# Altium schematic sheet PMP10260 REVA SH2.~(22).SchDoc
size 431 x 279 mm; Date: Not shown in title block; ApprovedBy: Not shown in title block; CheckedBy: Not shown in title block; Author: Not shown in title block; CompanyName: Not shown in title block; Engineer: Not shown in title block; Organization: Not shown in title block; Address1: Not shown in title block; Address2: Not shown in title block; Address3: Not shown in title block; Address4: Not shown in title block; DocumentNumber: 2; Revision: Use project parameter SCH_Rev; SheetNumber: 2; SheetTotal: 3; PageSetup: Record=PageOptions|CenterHorizontal=True|CenterVertical=True|PrintScale=1.00|XCorrection=1.00|YCorrection=1.00|PrintKind=0|BorderSize=5000000|LeftOffset=0|BottomOffset=0|Orientation=2|PaperLength=1000|PaperWidth=1000|Scale=100|PaperSource=15|PrintQuality=600|MediaType=1|DitherType=10|PaperKind=Letter|PrintScaleMode=1
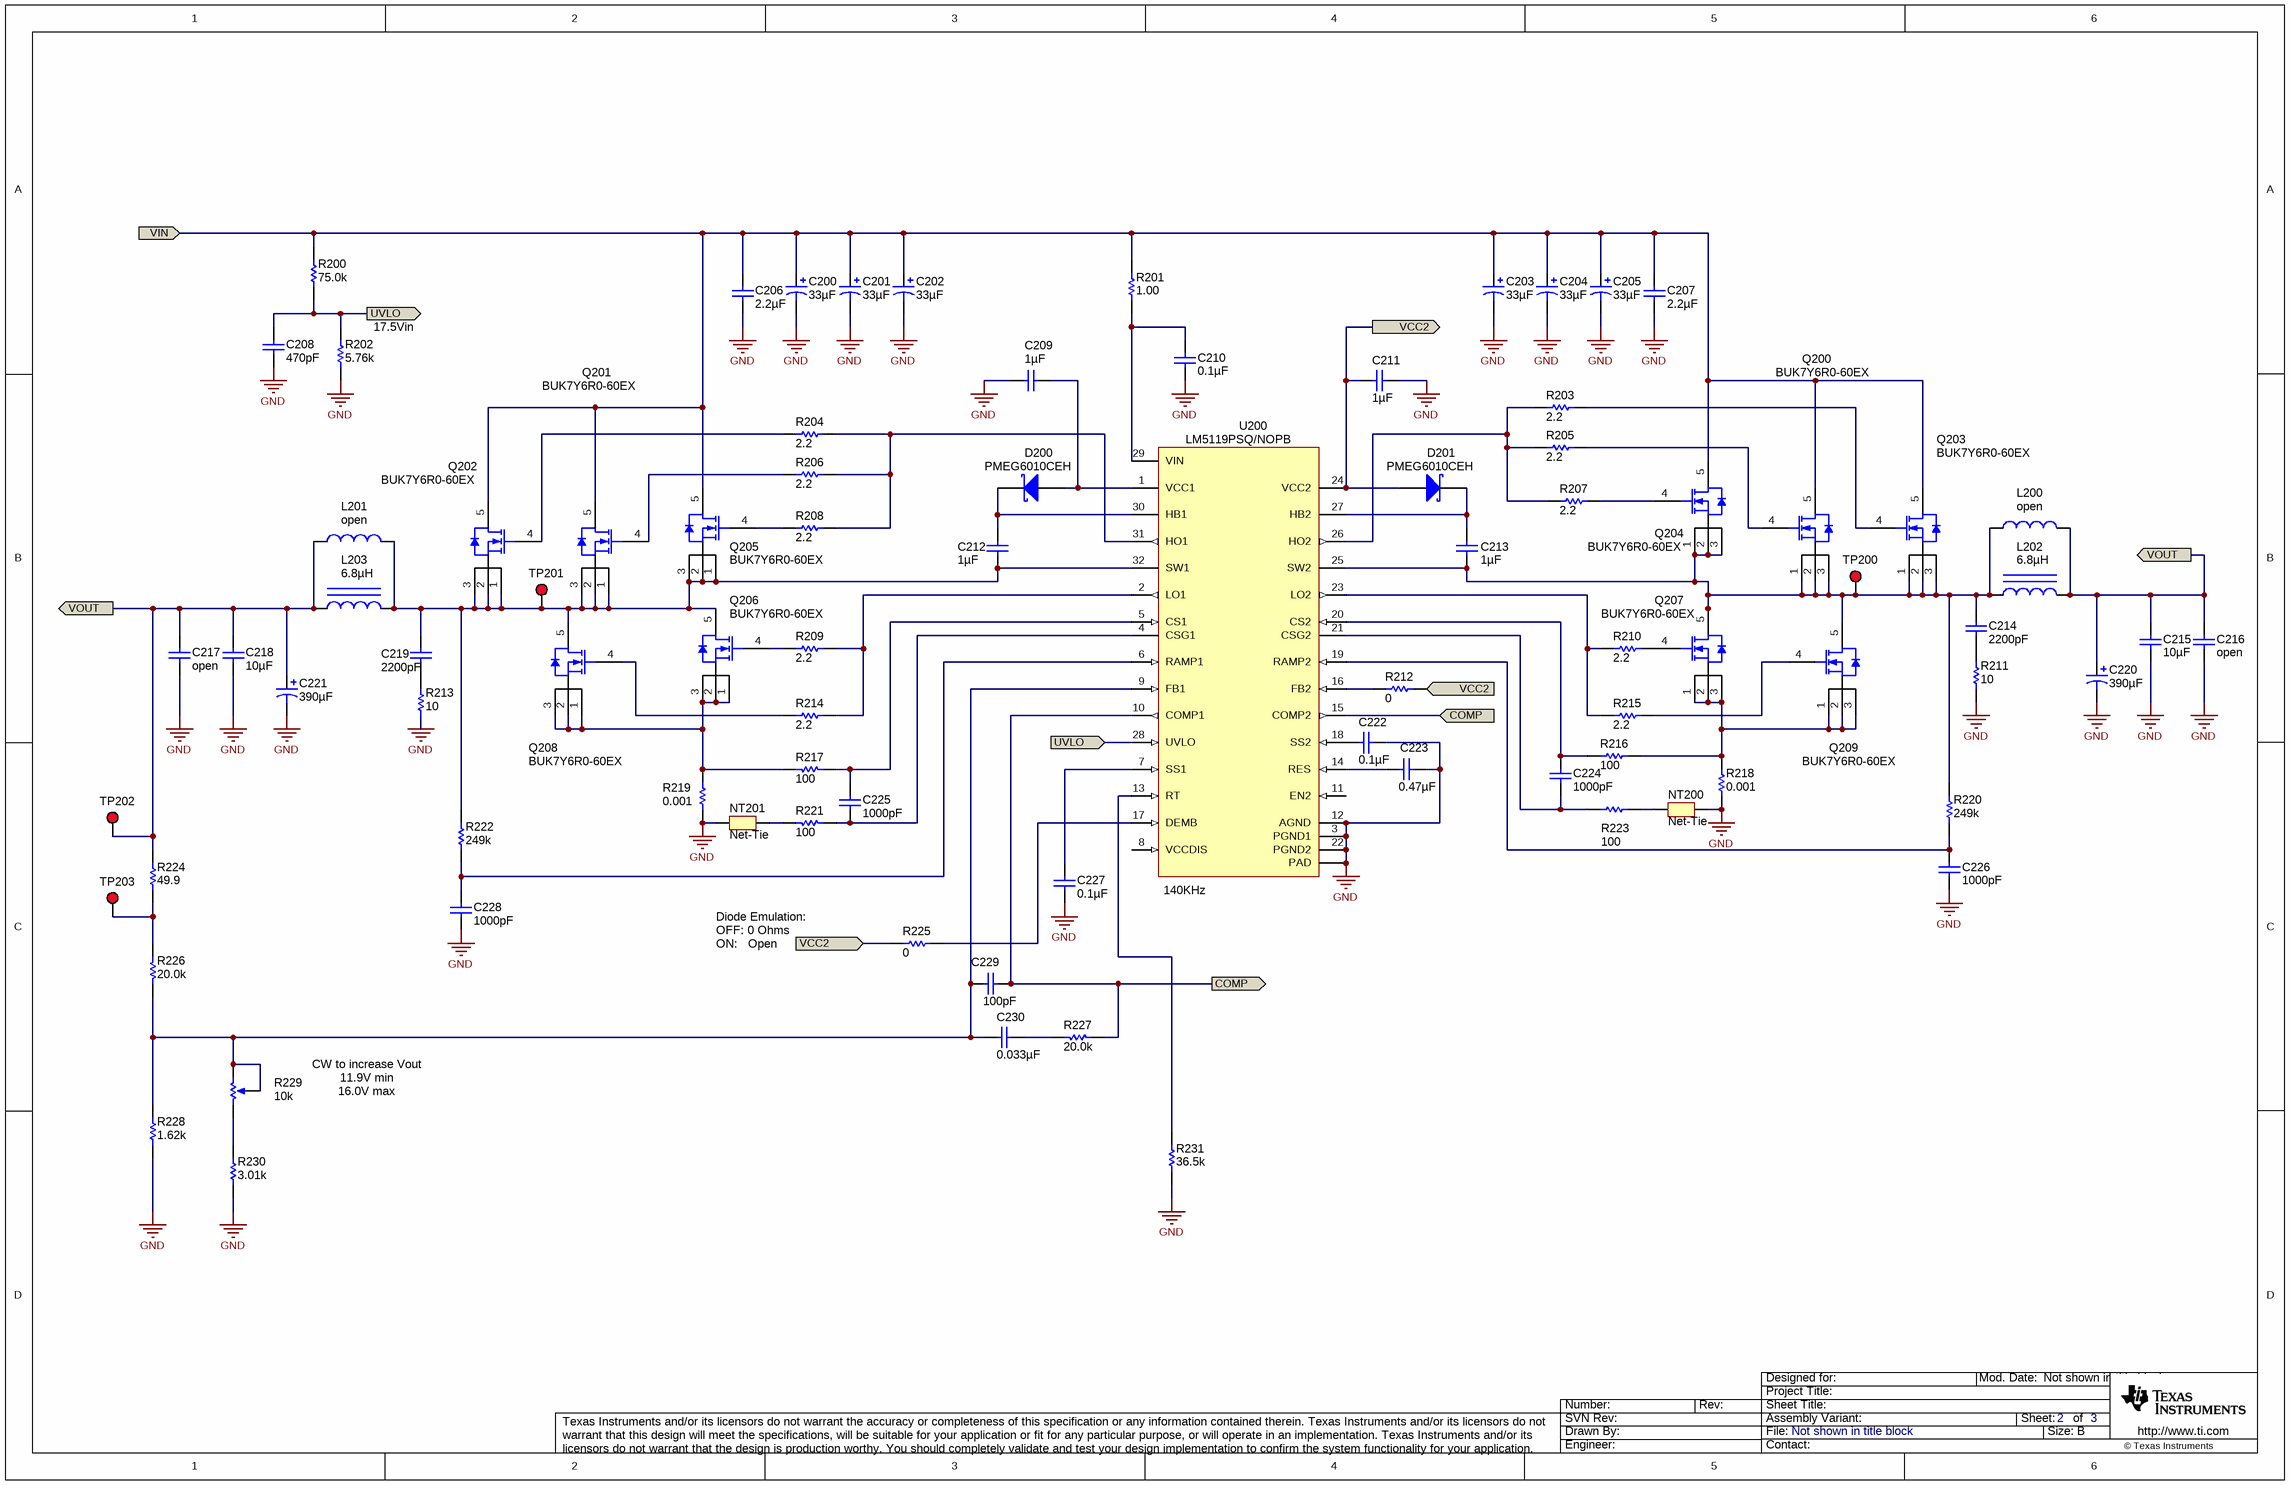
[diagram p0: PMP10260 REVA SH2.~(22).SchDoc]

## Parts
C200  ValueDisplayed: 33µF  [SXV_E12]  (hidden comment: 63SXV33M)
C201  ValueDisplayed: 33µF  [SXV_E12]  (hidden comment: 63SXV33M)
C202  ValueDisplayed: 33µF  [SXV_E12]  (hidden comment: 63SXV33M)
C203  ValueDisplayed: 33µF  [SXV_E12]  (hidden comment: 63SXV33M)
C204  ValueDisplayed: 33µF  [SXV_E12]  (hidden comment: 63SXV33M)
C205  ValueDisplayed: 33µF  [SXV_E12]  (hidden comment: 63SXV33M)
C206  ValueDisplayed: 2.2µF  [1210]  (hidden comment: GRM32ER72A225KA35L)
C207  ValueDisplayed: 2.2µF  [1210]  (hidden comment: GRM32ER72A225KA35L)
C208  ValueDisplayed: 470pF  [0603]  (hidden comment: C1608C0G1H471J)
C209  ValueDisplayed: 1µF  [0603L]  (hidden comment: C1608X7R1E105K080AB)
C210  ValueDisplayed: 0.1µF  [0805_HV]  (hidden comment: C2012X7R2A104K)
C211  ValueDisplayed: 1µF  [0603L]  (hidden comment: C1608X7R1E105K080AB)
C212  ValueDisplayed: 1µF  [0603L]  (hidden comment: C1608X7R1E105K080AB)
C213  ValueDisplayed: 1µF  [0603L]  (hidden comment: C1608X7R1E105K080AB)
C214  ValueDisplayed: 2200pF  [0603L]  (hidden comment: C0603C222K5RAC)
C215  ValueDisplayed: 10µF  [1210L]  (hidden comment: GMK325AB7106MM-T)
C216  ValueDisplayed: open  [1210]
C217  ValueDisplayed: open  [1210]
C218  ValueDisplayed: 10µF  [1210L]  (hidden comment: GMK325AB7106MM-T)
C219  ValueDisplayed: 2200pF  [0603L]  (hidden comment: C0603C222K5RAC)
C220  ValueDisplayed: 390µF  [SM_RADIAL_8MM]  (hidden comment: 20SVPF390M)
C221  ValueDisplayed: 390µF  [SM_RADIAL_8MM]  (hidden comment: 20SVPF390M)
C222  ValueDisplayed: 0.1µF  [0603L]  (hidden comment: C1608X7R1H104K)
C223  ValueDisplayed: 0.47µF  [0603L]  (hidden comment: C0603C474K4RACTU)
C224  ValueDisplayed: 1000pF  [0603]  (hidden comment: C1608C0G1H102J)
C225  ValueDisplayed: 1000pF  [0603]  (hidden comment: C1608C0G1H102J)
C226  ValueDisplayed: 1000pF  [0603]  (hidden comment: C1608C0G1H102J)
C227  ValueDisplayed: 0.1µF  [0603L]  (hidden comment: C1608X7R1H104K)
C228  ValueDisplayed: 1000pF  [0603]  (hidden comment: C1608C0G1H102J)
C229  ValueDisplayed: 100pF  [0603]  (hidden comment: C1608C0G1H101J)
C230  ValueDisplayed: 0.033µF  [0603]  (hidden comment: GRM188R71H333KA61D)
D200  PMEG6010CEH  [SOD-123F]
D201  PMEG6010CEH  [SOD-123F]
L200  ValueDisplayed: open  [SER29XX]
L201  ValueDisplayed: open  [SER29XX]
L202  ValueDisplayed: 6.8µH  [SER2915]  (hidden comment: SER2915H-682KL)
L203  ValueDisplayed: 6.8µH  [SER2915]  (hidden comment: SER2915H-682KL)
NT200  Net-Tie  [Net-Tie_10mil]  (net tie, no BOM)
NT201  Net-Tie  [Net-Tie_10mil]  (net tie, no BOM)
Q200  BUK7Y6R0-60EX  [LFPAK56]
Q201  BUK7Y6R0-60EX  [LFPAK56]
Q202  BUK7Y6R0-60EX  [LFPAK56]
Q203  BUK7Y6R0-60EX  [LFPAK56]
Q204  BUK7Y6R0-60EX  [LFPAK56]
Q205  BUK7Y6R0-60EX  [LFPAK56]
Q206  BUK7Y6R0-60EX  [LFPAK56]
Q207  BUK7Y6R0-60EX  [LFPAK56]
Q208  BUK7Y6R0-60EX  [LFPAK56]
Q209  BUK7Y6R0-60EX  [LFPAK56]
R200  value 75.0k  [0603]  (hidden comment: CRCW060375K0FKEA)
R201  value 1.00  [0805_HV]  (hidden comment: CRCW08051R00FKEA)
R202  value 5.76k  [0603]  (hidden comment: CRCW06035K76FKEA)
R203  value 2.2  [0603L]  (hidden comment: CRCW06032R20JNEA)
R204  value 2.2  [0603L]  (hidden comment: CRCW06032R20JNEA)
R205  value 2.2  [0603L]  (hidden comment: CRCW06032R20JNEA)
R206  value 2.2  [0603L]  (hidden comment: CRCW06032R20JNEA)
R207  value 2.2  [0603L]  (hidden comment: CRCW06032R20JNEA)
R208  value 2.2  [0603L]  (hidden comment: CRCW06032R20JNEA)
R209  value 2.2  [0603L]  (hidden comment: CRCW06032R20JNEA)
R210  value 2.2  [0603L]  (hidden comment: CRCW06032R20JNEA)
R211  value 10  [2010M]  (hidden comment: CRCW201010R0JNEFHP)
R212  value 0  [0603L]  (hidden comment: CRCW06030000Z0EA)
R213  value 10  [2010M]  (hidden comment: CRCW201010R0JNEFHP)
R214  value 2.2  [0603L]  (hidden comment: CRCW06032R20JNEA)
R215  value 2.2  [0603L]  (hidden comment: CRCW06032R20JNEA)
R216  value 100  [0603L]  (hidden comment: RC0603FR-07100RL)
R217  value 100  [0603L]  (hidden comment: RC0603FR-07100RL)
R218  value 0.001  [2512M]  (hidden comment: ERJ-M1WTF1M0U)
R219  value 0.001  [2512M]  (hidden comment: ERJ-M1WTF1M0U)
R220  value 249k  [0603]  (hidden comment: CRCW0603249KFKEA)
R221  value 100  [0603L]  (hidden comment: RC0603FR-07100RL)
R222  value 249k  [0603]  (hidden comment: CRCW0603249KFKEA)
R223  value 100  [0603L]  (hidden comment: RC0603FR-07100RL)
R224  value 49.9  [0603]  (hidden comment: CRCW060349R9FKEA)
R225  value 0  [0603L]  (hidden comment: CRCW06030000Z0EA)
R226  value 20.0k  [0603L]  (hidden comment: CRCW060320K0FKEA)
R227  value 20.0k  [0603]  (hidden comment: CRCW060320K0FKEA)
R228  value 1.62k  [0603]  (hidden comment: CRCW06031K62FKEA)
R229  value 10k  [TRIM_3224W]  (hidden comment: 3224W-2-103E)
R230  value 3.01k  [0603]  (hidden comment: CRCW06033K01FKEA)
R231  value 36.5k  [0603]  (hidden comment: CRCW060336K5FKEA)
TP200  5010  [Keystone5010]  (value not drawn)
TP201  5010  [Keystone5010]  (value not drawn)
TP202  5010  [Keystone5010]  (value not drawn)
TP203  5010  [Keystone5010]  (value not drawn)
U200  LM5119PSQ/NOPB  [RTV0032A]

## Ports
COMP, UVLO, VCC2, VIN, VOUT

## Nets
GND: C200.2(-) C201.2(-) C202.2(-) C203.2(-) C204.2(-) C205.2(-) C206.2 C207.2 C208.2 C209.2 C210.2 C211.2 C215.2 C216.2 C217.2 C218.2 C220.2(-) C221.2(-) C222.1 C223.1 C226.2 C227.2 C228.2 NT200.2 NT201.1 R202.1 R211.1 R213.1 R218.1 R219.1 R228.1 R230.1 R231.1 U200.3(PGND1) U200.12(AGND) U200.22(PGND2) U200.33(PAD)
COMP: C229.1 R227.1 U200.10(COMP1) U200.15(COMP2) ; port COMP
UVLO: C208.1 R200.1 R202.2 U200.28(UVLO) ; port UVLO
VCC2: C211.1 D201.2(A) R212.2 R225.1 U200.24(VCC2) ; port VCC2
VIN: C200.1(+) C201.1(+) C202.1(+) C203.1(+) C204.1(+) C205.1(+) C206.1 C207.1 Q200.5(D) Q201.5(D) Q202.5(D) Q203.5(D) Q204.5(D) Q205.5(D) R200.2 R201.1 ; port VIN
VOUT: C215.1 C216.1 C217.1 C218.1 C220.1(+) C221.1(+) L200.2 L201.1 L202.2 L203.1 R224.2 TP202.1 ; port VOUT
NetC209_1: C209.1 D200.2(A) U200.1(VCC1)
NetC210_1: C210.1 R201.2 U200.29(VIN)
NetC212_1: C212.1 D200.1(K) U200.30(HB1)
NetC212_2: C212.2 C219.1 L201.2 L203.2 Q201.1(S) Q201.2(S) Q201.3(S) Q202.1(S) Q202.2(S) Q202.3(S) Q205.1(S) Q205.2(S) Q205.3(S) Q206.5(D) Q208.5(D) R222.2 TP201.1 U200.32(SW1)
NetC213_1: C213.1 D201.1(K) U200.27(HB2)
NetC213_2: C213.2 C214.1 L200.1 L202.1 Q200.1(S) Q200.2(S) Q200.3(S) Q203.1(S) Q203.2(S) Q203.3(S) Q204.1(S) Q204.2(S) Q204.3(S) Q207.5(D) Q209.5(D) R220.2 TP200.1 U200.25(SW2)
NetC214_2: C214.2 R211.2
NetC219_2: C219.2 R213.2
NetC222_2: C222.2 U200.18(SS2)
NetC223_2: C223.2 U200.14(RES)
NetC224_1: C224.1 R216.1 U200.20(CS2)
NetC224_2: C224.2 R223.1 U200.21(CSG2)
NetC225_1: C225.1 R217.1 U200.5(CS1)
NetC225_2: C225.2 R221.1 U200.4(CSG1)
NetC226_1: C226.1 R220.1 U200.19(RAMP2)
NetC227_1: C227.1 U200.7(SS1)
NetC228_1: C228.1 R222.1 U200.6(RAMP1)
NetC229_2: C229.2 C230.2 R226.1 R228.2 R229.1(CCW) R229.2(WIPER) U200.9(FB1)
NetC230_1: C230.1 R227.2
NetNT200_1: NT200.1 R223.2
NetNT201_2: NT201.2 R221.2
NetQ200_4: Q200.4(G) R205.2
NetQ201_4: Q201.4(G) R206.1
NetQ202_4: Q202.4(G) R204.1
NetQ203_4: Q203.4(G) R203.2
NetQ204_4: Q204.4(G) R207.2
NetQ205_4: Q205.4(G) R208.1
NetQ206_1: Q206.1(S) Q206.2(S) Q206.3(S) Q208.1(S) Q208.2(S) Q208.3(S) R217.2 R219.2
NetQ206_4: Q206.4(G) R209.1
NetQ207_1: Q207.1(S) Q207.2(S) Q207.3(S) Q209.1(S) Q209.2(S) Q209.3(S) R216.2 R218.2
NetQ207_4: Q207.4(G) R210.2
NetQ208_4: Q208.4(G) R214.1
NetQ209_4: Q209.4(G) R215.2
NetR203_1: R203.1 R205.1 R207.1 U200.26(HO2)
NetR204_2: R204.2 R206.2 R208.2 U200.31(HO1)
NetR209_2: R209.2 R214.2 U200.2(LO1)
NetR210_1: R210.1 R215.1 U200.23(LO2)
NetR212_1: R212.1 U200.16(FB2)
NetR224_1: R224.1 R226.2 TP203.1
NetR225_2: R225.2 U200.17(DEMB)
NetR229_3: R229.3(CW) R230.2
NetR231_2: R231.2 U200.13(RT)

Not connected (* = marked no-connect by the designer): L200 3; L201 3; U200 8(VCCDIS) 11(EN2)

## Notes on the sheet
- (near R202) 17.5Vin
- (near U200) 140KHz
- Diode Emulation:
- ON:   Open
- OFF: 0 Ohms
- 11.9V min
- 16.0V max
- CW to increase Vout

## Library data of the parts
C200-C205 = 63SXV33M: CAP, OS-CON, 33uF, 63V, +/-20%, 0.025 ohm, 8.0x11.9mm SMD; Manufacturer: Panasonic; Polarized: Y; CompType: Capacitor; U/M: EA; Cap_F: 0.000033; Tolerance_%: 20; VDC_V: 63; ESR_Ohm: 0.025; IRMS_A: 2.95; TaMin_C: -55; TaMax_C: 105
C206 C207 = GRM32ER72A225KA35L: CAP, CERM, 2.2uF, 100V, +/-10%, X7R, 1210; Manufacturer: MuRata; Polarized: N; CompType: Capacitor; U/M: EA; Cap_F: 0.0000022; Tolerance_%: 10; ESR_Ohm: 0.007; Value1: 0.007 ohm; VDC_V: 100; IRMS_A: 4.4; TaMin_C: -55; TaMax_C: 125
C208 = C1608C0G1H471J: CAP, CERM, 470pF, 50V, +/-5%, C0G/NP0, 0603; Manufacturer: TDK; Polarized: N; CompType: Capacitor; U/M: EA; Cap_F: 0.00000000047; Tolerance_%: 5; ESR_Ohm: 0.0922; Value1: 0.0922 ohm; VDC_V: 50; TaMin_C: -55; TaMax_C: 125
C209 C211-C213 = C1608X7R1E105K080AB: CAP, CERM, 1uF, 25V, +/-10%, X7R, 0603; Manufacturer: TDK; Polarized: N; CompType: Capacitor; U/M: EA; Cap_F: 0.000001; Tolerance_%: 10; Value1: Unknown; VDC_V: 25; TaMin_C: -55; TaMax_C: 125; Cap_Case: 0603
C210 = C2012X7R2A104K: CAP, CERM, 0.1uF, 100V, +/-10%, X7R, 0805; Manufacturer: TDK; Polarized: N; CompType: Capacitor; U/M: EA; Cap_F: 0.0000001; Tolerance_%: 10; ESR_Ohm: 0.0158; Value1: 0.0158 ohm; VDC_V: 100; TaMin_C: -55; TaMax_C: 125; Cap_Case: 0805
C214 C219 = C0603C222K5RAC: CAP, CERM, 2200pF, 50V, +/-10%, X7R, 0603; Manufacturer: Kemet; Polarized: N; CompType: Capacitor; U/M: EA; Cap_F: 0.0000000022; Tolerance_%: 10; Value1: Unknown; VDC_V: 50; TaMin_C: -55; TaMax_C: 125; Cap_Case: 0603
C215 C218 = GMK325AB7106MM-T: CAP, CERM, 10uF, 35V, +/-20%, X7R, 1206; Manufacturer: Taiyo Yuden; Polarized: N; CompType: Capacitor; U/M: EA; Cap_F: 0.00001; Tolerance_%: 20; Value1: Unknown; VDC_V: 35; TaMin_C: -55; TaMax_C: 125; Cap_Case: 1210
C216 C217 = C3225X7R1H335M: CAP, CERM, open, 1210; Manufacturer: TDK; Polarized: N; CompType: Capacitor; Value: 10uF; U/M: EA; Cap_F: 0.0000033; Tolerance_%: 20; Value1: Unknown; VDC_V: 50; Value2: 50V; TempCo: X5R; TaMin_C: -55; TaMax_C: 125
C220 C221 = 20SVP100M: CAP, OS-CON, 390uF, 20V, +/-20%, 0.014 ohm, 8x10 SMD; Manufacturer: Sanyo; Polarized: Y; CompType: Capacitor; U/M: EA; Cap_F: 0.0001; Tolerance_%: 20; ESR_Ohm: 0.024; IRMS_A: 3.32; TaMin_C: -55; TaMax_C: 105; Cap_Case: 8.3x8.3x11.9
C222 C227 = C1608X7R1H104K: CAP, CERM, 0.1uF, 50V, +/-10%, X7R, 0603; Manufacturer: TDK; Polarized: N; CompType: Capacitor; U/M: EA; Cap_F: 0.0000001; Tolerance_%: 10; ESR_Ohm: 0.017; Value1: 0.017 ohm; VDC_V: 50; TaMin_C: -55; TaMax_C: 125; Cap_Case: 0603
C223 = C0603C474K4RACTU: CAP, CERM, 0.47uF, 16V, +/-10%, X7R, 0603; Manufacturer: Kemet; Polarized: N; CompType: Capacitor; U/M: EA; Cap_F: 0.00000047; Tolerance_%: 10; Value1: Unknown; VDC_V: 16; TaMin_C: -55; TaMax_C: 125; Cap_Case: 0603
C224-C226 C228 = C1608C0G1H102J: CAP, CERM, 1000pF, 50V, +/-5%, C0G/NP0, 0603; Manufacturer: TDK; Polarized: N; CompType: Capacitor; U/M: EA; Cap_F: 0.000000001; Tolerance_%: 5; ESR_Ohm: 0.0563; Value1: 0.0563 ohm; VDC_V: 50; TaMin_C: -55; TaMax_C: 125
C229 = C1608C0G1H101J: CAP, CERM, 100pF, 50V, +/-5%, C0G/NP0, 0603; Manufacturer: TDK; Polarized: N; CompType: Capacitor; U/M: EA; Cap_F: 0.0000000001; Tolerance_%: 5; ESR_Ohm: 0.1679; Value1: 0.1679 ohm; VDC_V: 50; TaMin_C: -55; TaMax_C: 125
C230 = GRM188R71H333KA61D: CAP, CERM, 0.033uF, 50V, +/-10%, X7R, 0603; Manufacturer: MuRata; Polarized: N; CompType: Capacitor; U/M: EA; Cap_F: 0.000000033; Tolerance_%: 10; Value1: Unknown; VDC_V: 50; TaMin_C: -55; TaMax_C: 125
D200 D201 = PMEG6010CEH,115: Diode, Schottky, 60V, 1A, SOD-123F; Manufacturer: NXP Semiconductor; U/M: EA; Vf_V: 0.57; Value2: 0.57V; Io_A: 1; Vr_V: 60; TJmax_C: 150
L200 L201 = SER29XX: Inductor, open, TH; SymbolCreator: a0411947; Ind_H: 6.8E-6; Imax_A: 40
L202 L203 = SER2915H-682KL: Inductor, Shielded E Core, Ferrite, 6.8uH, 30A, 0.00186 ohm, SMD; Manufacturer: Coilcraft; Ind_H: 6.8E-6; Imax_A: 30; Irms: 30A @ 40C rise; Isat: 36.2A @ 30% inductance drop; U/M: EA
NT200 NT201 = Net-Tie: Single point connection between nets.; SymbolCreator: codlsc
Q200-Q209 = BUK7Y6R0-60EX: MOSFET, N-CH, 60V, 100A, SOT669; Manufacturer: NXP Semiconductor; Alternate Manufacturer: None; SymbolCreator: a0412235; U/M: EA; ChType: N; VdsMax_V: 60; Value1: ? ohm; Value2: 45.4 nC; QgTyp_nC: 45.4; Vgs_V: 20; IdsMax_A: 100
R200 = CRCW060375K0FKEA: RES, 75.0k ohm, 1%, 0.1W, 0603; Manufacturer: Vishay-Dale; CompType: Resistor; Res_ohm: 75000; Value_Code: 75k0; Tolerance_%: 1; Power_W: 0.1; VDC_V: 75; TempCo: 100 ppm/C; EIA_Code: E96; U/M: EA
R201 = CRCW08051R00FKEA: RES, 1.00 ohm, 1%, 0.125W, 0805; Manufacturer: Vishay-Dale; CompType: Resistor; Res_ohm: 1; Value_Code: 1R00; Power_W: 0.125; VDC_V: 150; TempCo: 100 ppm/C; EIA_Code: E96; U/M: EA
R202 = CRCW06035K76FKEA: RES, 5.76k ohm, 1%, 0.1W, 0603; Manufacturer: Vishay-Dale; CompType: Resistor; Res_ohm: 5760; Value_Code: 5k76; Tolerance_%: 1; Power_W: 0.1; VDC_V: 75; TempCo: 100 ppm/C; EIA_Code: E96; U/M: EA
R203-R210 R214 R215 = CRCW06032R20JNEA: RES, 2.2 ohm, 5%, 0.1W, 0603; Manufacturer: Vishay-Dale; CompType: Resistor; Value_Code: 2R20; Tolerance_%: 5; Power_W: 0.1; VDC_V: 75; TempCo: 200 ppm/C; EIA_Code: E24; U/M: EA
R211 R213 = CRCW20101R00JNEFHP: RES, 10 ohm, 5%, 1W, 2010; Manufacturer: Vishay-Dale; CompType: Resistor; Res_ohm: 1; Value_Code: 1R00; Tolerance_%: 5; VDC_V: 400; TempCo: 200 ppm/C; EIA_Code: E24; U/M: EA
R212 R225 = CRCW06030000Z0EA: RES, 0 ohm, 5%, 0.1W, 0603; Manufacturer: Vishay-Dale; CompType: Resistor; Value_Code: 0000; Tolerance_%: 5; Power_W: 0.1; VDC_V: 75; TempCo: 200 ppm/C; EIA_Code: E24; U/M: EA
R216 R217 R221 R223 = RC0603FR-07100RL: RES, 100 ohm, 1%, 0.1W, 0603; Manufacturer: Yageo America; CompType: Resistor; Value_Code: 100R; Tolerance_%: 1; Power_W: 0.1; VDC_V: 150; TempCo: 200 ppm/C; EIA_Code: E96; U/M: EA
R218 R219 = ERJ-M1WTF1M0U: RES, 0.001 ohm, 1%, 1W, 2512; Manufacturer: Panasonic; CompType: Resistor; Value_Code: R001; Tolerance_%: 1; TempCo: ppm/C; EIA_Code: E96; U/M: EA
R220 R222 = CRCW0603249KFKEA: RES, 249k ohm, 1%, 0.1W, 0603; Manufacturer: Vishay-Dale; CompType: Resistor; Res_ohm: 249000; Tolerance_%: 1; Power_W: 0.1; VDC_V: 75; TempCo: 100 ppm/C; EIA_Code: E96; U/M: EA
R224 = CRCW060349R9FKEA: RES, 49.9 ohm, 1%, 0.1W, 0603; Manufacturer: Vishay-Dale; CompType: Resistor; Value_Code: 49R9; Tolerance_%: 1; Power_W: 0.1; VDC_V: 75; TempCo: 100 ppm/C; EIA_Code: E96; U/M: EA
R226 R227 = CRCW060320K0FKEA: RES, 20.0k ohm, 1%, 0.1W, 0603; Manufacturer: Vishay-Dale; CompType: Resistor; Res_ohm: 20000; Value_Code: 20k0; Tolerance_%: 1; Power_W: 0.1; VDC_V: 75; TempCo: 100 ppm/C; EIA_Code: E96; U/M: EA
R228 = CRCW06031K62FKEA: RES, 1.62k ohm, 1%, 0.1W, 0603; Manufacturer: Vishay-Dale; CompType: Resistor; Res_ohm: 1620; Value_Code: 1k62; Tolerance_%: 1; Power_W: 0.1; VDC_V: 75; TempCo: 100 ppm/C; EIA_Code: E96; U/M: EA
R229 = 3224W-2-103E: TRIMMER, 10K, 0.25W, SMD; Manufacturer: Bourns; Sim Note: Enter the Resistance value and the set point into parameter fields.; SymbolCreator: a0412235
R230 = CRCW06033K01FKEA: RES, 3.01k ohm, 1%, 0.1W, 0603; Manufacturer: Vishay-Dale; CompType: Resistor; Res_ohm: 3010; Value_Code: 3k01; Tolerance_%: 1; Power_W: 0.1; VDC_V: 75; TempCo: 100 ppm/C; EIA_Code: E96; U/M: EA
R231 = CRCW060336K5FKEA: RES, 36.5k ohm, 1%, 0.1W, 0603; Manufacturer: Vishay-Dale; CompType: Resistor; Res_ohm: 36500; Value_Code: 36k5; Tolerance_%: 1; Power_W: 0.1; VDC_V: 75; TempCo: 100 ppm/C; EIA_Code: E96; U/M: EA
TP200-TP203 = 5010: Test Point, Multipurpose, Red, TH; Manufacturer: Keystone; CompType: Test Point Loop; U/M: EA
U200 = LM5119PSQ/NOPB: LM5119/LM5119Q Wide Input Range Dual Synchronous Buck Controller, RTV0032A; Alternate Manufacturer: None; Manufacturer: Texas Instruments; SymbolCreator: a0411947; CompType: IC; U/M: EA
